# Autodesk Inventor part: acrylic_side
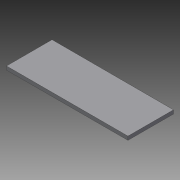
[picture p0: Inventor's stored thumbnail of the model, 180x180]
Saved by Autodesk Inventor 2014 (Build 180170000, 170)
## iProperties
Created: 2014-06
Part Number: acrylic_side
Material: Generic
Document SubType Name: Modeling
Designer: t_emanb
Density: 1 g/cm^3
Appearance: Default
Author: t_emanb
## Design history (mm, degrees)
sketch "Sketch1"
  geometry: L1 (0, 0)-(101.6, 0); L2 (101.6, 0)-(101.6, 38.1); L3 (101.6, 38.1)-(0, 38.1); L4 (0, 38.1)-(0, 0)
  constraints: 8 end point, 2 parallel, 1 horizontal, 1 perpendicular
  dimensions: "d0" = 38.1 distance of L3.end L1.start; "d1" = 101.6 distance of L1.start L1.end
extrude "Extrusion1" new body sketch "Sketch1" distance "d2" = 3.048; taper "d3" = 0 deg
body "Solid1"
